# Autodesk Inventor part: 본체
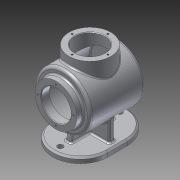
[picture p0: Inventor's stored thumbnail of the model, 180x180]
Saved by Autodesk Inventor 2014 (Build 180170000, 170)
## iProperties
Created: 2016-04
Part Number: 본체
Material: Aluminum 6061
Document SubType Name: Modeling
Designer: user
Density: 2.71 g/cm^3
Appearance: Aluminum - Flat
Mass: 961.482 g
Surface Area: 1326.62 cm^2
Volume: 354.79 cm^3
Author: user
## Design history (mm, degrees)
sketch "Sketch1"
  geometry: L1 (45.841, 110.899)-(-45.841, -110.899); A1 r 120 centre (0, 0) between (45.841, 110.899) and (-45.841, -110.899); 1 further point
  constraints: 2 end point, 2 point on circle, 1 centre point, 1 coincident, 1 midpoint
  dimensions: "d0" = 240 diameter of A1
revolve "Revolution1" sketch "Sketch1" stored, may be unused: angle "d1" = 90 deg
sketch "Sketch2"
  geometry: L1 (109.378, 41.54)-(-109.378, -41.54); A1 r 117 centre (0, 0) between (109.378, 41.54) and (-109.378, -41.54); 1 further point
  constraints: 2 end point, 2 point on circle, 1 centre point, 1 coincident, 1 midpoint
  dimensions: "d2" = 234 diameter of A1
revolve "Revolution2" sketch "Sketch2" stored, may be unused: angle "d3" = 90 deg
workplane "Work Plane1"
sketch "Sketch3"
  geometry: L1 (-186.134, 164.451)-(186.134, 164.451); L2 (186.134, 164.451)-(186.134, -164.451); L3 (186.134, -164.451)-(-186.134, -164.451); L4 (-186.134, -164.451)-(-186.134, 164.451); 3 further points
  constraints: 8 end point, 2 midpoint, 2 parallel, 1 horizontal, 1 horizontal alignment, 1 perpendicular, 1 vertical alignment
  dimensions: "d5" = 372.26754 distance of L1.start L1.end; "d6" = 328.90283 distance of L3.end L1.start
extrude "Extrusion1" cut sketch "Sketch3" distance "d7" = 11111; taper "d8" = 0 deg
sketch "Sketch5"
  geometry: C1 r 39.862 at (0, 0) reference; C2 r 50 at (0, 0); C3 r 47 at (0, 0)
  constraints: 3 coincident, 2 centre point
  dimensions: "d9" = 100 diameter of C2; "d88" = 94 diameter of C3
extrude "Extrusion2" join sketch "Sketch5" distance "d10" = 100; taper "d11" = 0 deg
sketch "Sketch6"
  geometry: C1 r 50 at (0, 0) reference; C2 r 38 at (0, 0)
  constraints: 1 centre point, 1 coincident
  dimensions: "d12" = 76 diameter of C2
extrude "Extrusion3" join sketch "Sketch6" distance "d13" = 12; taper "d14" = 0 deg
workplane "Work Plane2"
sketch "Sketch7"
  geometry: C1 r 50 at (0, 0) reference; C2 r 47 at (0, 0); 1 further point
  constraints: 1 centre point
  dimensions: "d15" = 3 radial gap between concentric circles of C1 C2
extrude "Extrusion4" cut sketch "Sketch7" stored distance "d16" = 94; taper "d17" = 0 deg
workplane "Work Plane3"
sketch "Sketch8"
  geometry: L1 (-127.5, 0)-(7.5, 0); L2 (-77.5, 50)-(-42.5, 50); L3 (-77.5, -50)-(-42.5, -50); L4 (-110, 50)-(-10, 50) reference; A1 r 50 centre (-42.5, 0) between (-42.5, 50) and (-42.5, -50); A2 r 50 centre (-77.5, 0) between (-77.5, 50) and (-77.5, -50); 3 further points
  constraints: 6 end point, 4 point on circle, 3 horizontal alignment, 3 tangent, 2 centre point, 2 midpoint, 1 horizontal, 1 parallel, 1 vertical alignment
  dimensions: "d21" = 135 distance of L1.start L1.end; "d23" = 100 diameter of A1; "d24" = 100 diameter of A2; "d25" = 50 distance of L1.start A2.centre; "d26" = 50 distance of L1.end A1.centre
extrude "Extrusion5" join sketch "Sketch8" distance "d27" = 10; taper "d28" = 0 deg
sketch "Sketch9"
  geometry: L1 (-50, -69)-(50, -69) reference; L2 (50, -69)-(50, -79) reference; L3 (50, -79)-(-50, -79) reference; L4 (-50, -79)-(-50, -69) reference; L5 (-40, -69)-(-40, -24.678); L6 (40, -24.678)-(40, -69); C1 r 47 at (0, 0) reference; C2 r 50 at (0, 0) reference; A1 r 47 centre (0, 0) between (-40, -24.678) and (40, -24.678); 1 further point
  constraints: 4 end point, 2 point on circle, 2 point on line, 1 centre point, 1 coincident, 1 concentric, 1 parallel, 1 perpendicular
  dimensions: "d30" = 40 distance from line of point (0, 0) L5; "d31" = 40 horizontal distance of L6.start point (0, 0)
extrude "Extrusion6" join sketch "Sketch9" stored distance "d32" = 10; taper "d33" = 0 deg
sketch "Sketch10"
  geometry: L1 (127.5, -69)-(77.5, -69) reference; L2 (65, -69)-(65, -30) reference; L3 (110, -50)-(10, -50) reference; L4 (77.5, -69)-(42.5, -69) reference; L5 (100, -69)-(96.65, -50); L6 (100, -69)-(152.824, -69); 1 further point
  constraints: 4 end point, 2 point on line, 1 horizontal
  dimensions: "d34" = 100 deg angle of L6 L5; "d35" = 35 distance from line of L5.start L2
feature "Rib1" sketch "Sketch10" dims "d36" = 1, "d37" = 10, "d38" = 0, "d39" = 0, "d40" = 1, "d41" = 1
mirror "Mirror1"
fillet "Fillet1" dims "d42" = 3
fillet "Fillet2" dims "d43" = 3
chamfer "Chamfer1" distance "d44" = 3; stored, may be unused: second distance "d45" = 2, angle "d46" = 45 deg
sketch "Sketch11"
  geometry: C1 r 38 at (0, 0) reference; C2 r 27 at (0, 0)
  constraints: 1 centre point, 1 coincident
  dimensions: "d47" = 54 diameter of C2
extrude "Extrusion7" cut sketch "Sketch11" distance "d48" = 15; taper "d49" = 0 deg
workplane "Work Plane4"
sketch "Sketch12"
  geometry: L1 (110, -50)-(10, -50) reference; C1 r 38 at (60, 0); 2 further points
  constraints: 1 centre point, 1 horizontal alignment, 1 midpoint, 1 vertical alignment
  dimensions: "d51" = 76 diameter of C1
extrude "Extrusion8" join sketch "Sketch12" stored distance "d52" = 15; taper "d53" = 0 deg
sketch "Sketch13"
  geometry: C1 r 38 at (0, 0) reference; C2 r 27 at (0, 0); 1 further point
  constraints: 1 centre point, 1 coincident
  dimensions: "d54" = 54 diameter of C2
extrude "Extrusion9" cut sketch "Sketch13" stored distance "d55" = 15; taper "d56" = 0 deg
fillet "Fillet4" dims "d58" = 5
fillet "Fillet5" dims "d59" = 3
chamfer "Chamfer2" distance "d60" = 1; stored, may be unused: second distance "d61" = 2, angle "d62" = 45 deg
chamfer "Chamfer3" distance "d63" = 1; stored, may be unused: second distance "d64" = 2, angle "d65" = 45 deg
sketch "Sketch14" dims "d66" = 65
  geometry: C1 r 28 at (0, 0) reference; 3 further points
  constraints: 1 coincident, 1 vertical alignment, 2 other
hole "Hole1" sketch "Sketch14" at (0, 32.5) diameter "d67" = 3.242; stored, may be unused: countersink angle "d71" = 90 deg, drill point angle "d73" = 118 deg; dims "d68" = 8, "d69" = 4, "d70" = 2, "d72" = 10
pattern_circular "Circular Pattern1" dims angle "d75" = 360 deg
sketch "Sketch15" dims "d77" = 65
  geometry: C1 r 28 at (0, 0) reference; 2 further points
  constraints: 1 coincident, 1 vertical alignment, 2 other
hole "Hole2" sketch "Sketch15" at (0, 32.5) diameter "d78" = 3.242; stored, may be unused: countersink angle "d82" = 90 deg, drill point angle "d84" = 118 deg; dims "d79" = 8, "d80" = 4, "d81" = 2, "d83" = 10
pattern_circular "Circular Pattern2" dims angle "d86" = 360 deg
workplane "Work Plane5"
sketch "Sketch18"
  geometry: 2 further points
  constraints: 1 coincident, 1 other
emboss "Emboss1" sketch "Sketch18" dims "d0" = 240, "d91" = 0.5, "d92" = 0
sketch "Sketch19"
  geometry: L1 (52, 37)-(52, 8) reference; L2 (68, 8)-(68, 37) reference; C1 r 5 at (6, 0); C2 r 5 at (114, 0); A1 r 47 centre (77.5, 0) between (77.5, -47) and (77.5, 47) reference; A2 r 47 centre (42.5, 0) between (42.5, 47) and (42.5, -47) reference; 1 further point
  constraints: 2 centre point, 2 horizontal alignment
  dimensions: "d93" = 10 diameter of C1; "d94" = 46 distance from line of L1 C1.centre; "d95" = 10 diameter of C2; "d96" = 46 distance from line of L2 C2.centre
extrude "Extrusion10" cut sketch "Sketch19" distance "d97" = 94; taper "d98" = 0 deg
fillet "Fillet6" dims "d99" = 3
fillet "Fillet7" dims "d100" = 2
body "Solid1"
node "Project Cut Edges1"
node "Project Cut Edges2"
other parameters: "d18" = -79, "d50" = -144
